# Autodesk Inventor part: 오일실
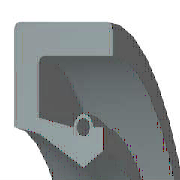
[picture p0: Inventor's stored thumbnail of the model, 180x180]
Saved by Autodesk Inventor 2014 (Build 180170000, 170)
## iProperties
IsCustomPart: 1
Created: 2015-12
Part Number: 오일실
Material: 고무
Description: 오일-실
Document SubType Name: Modeling
Standard: KS B 2804
Designer: mdu
Standards Organization: KS
Language: ko-KR
Size Designation: S - 15 30 7
Categories: <MemberInstance><Categories><Category DisplayName="샤프트 부품" InternalName="7f7aeb1f-a693-4053-b835-cee3144e0d98" Mnemonic="SHFT"><Category DisplayName="실링" Intern
Density: 1 g/cm^3
Appearance: 고무 - 검은색 - 버전 1.1
Mass: 1.76736 g
Surface Area: 26.6454 cm^2
Volume: 1.76736 cm^3
Author: mdu
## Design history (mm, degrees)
revolve "본체" stored, may be unused: angle "d17" = 90 deg
revolve "스프링1" stored, may be unused: angle "d18" = 90 deg
body "Solid1"
sketch "스케치1"
  geometry: L1 (0, 15)-(7, 15); L2 (7, 15)-(7, 13.75); L3 (7, 13.75)-(1.75, 13.75); L4 (0, 15)-(0, 9.6); L5 (0, 9.6)-(1.75, 9.25); L6 (1.75, 9.25)-(4.9, 7.5); L7 (4.9, 7.5)-(0, 7.5); L8 (6.3, 8.375)-(6.3, 9.6); L9 (0, 0)-(9.586, 0) reference; L10 (4.9, 7.5)-(6.3, 8.375); L11 (0, 18)-(0, -3) reference; L12 (-1.917, 0)-(11.503, 0) reference; L13 (4.2, 9.6)-(1.75, 10.09); L14 (1.75, 10.09)-(1.75, 13.75); L15 (6.3, 9.6)-(5.6, 9.6); C1 r 0.455 at (4.9, 9.6); A1 r 0.7 centre (4.9, 9.6) between (5.6, 9.6) and (4.2, 9.6)
  constraints: 26 end point, 5 horizontal alignment, 4 perpendicular, 2 centre point, 2 collinear, 2 horizontal, 2 parallel, 2 point on circle, 2 point on line, 2 vertical alignment, 1 coincident
  dimensions: "d0" = 30 diameter of L1 L9 (= SD2); "d1" = 16.75 diameter of L8.start L9 (= ABDM); "d2" = 1.25 distance of L1.end L2.end (computed from SD); "d3" = 0.91 diameter of C1 (= SPDI); "d4" = 1.4 diameter of A1 (= SPDA); "d5" = 15 diameter of L6.end L9 (= NND); "d6" = 18.5 diameter of L5.end L9 (= TKDM); "d7" = 19.2 diameter of L4.end L9 (= HLDM); "d8" = 4.9 distance from line of C1.centre L4 (= SPDST); "d9" = 6.3 distance between parallel lines of L8 L4 (= SDI); "d10" = 7 distance between parallel lines of L2 L4 (= SWDT); "d12" = 1.75 distance between parallel lines of L14 L4 (= SD)
fillet "모깎기1" dims "d11" = 0.3 (= RR)
other parameters: "SD2" = 30 [user parameter; used in 1 equation term], "SWDT" = 7 [user parameter; used in 1 equation term], "RR" = 0.3 [user parameter; used in 1 equation term], "SD" = 1.75 [user parameter; used in 2 equation terms], "NND" = 15 [user parameter; used in 1 equation term], "SPDA" = 1.4 [user parameter; used in 1 equation term], "SPDI" = 0.91 [user parameter; used in 1 equation term], "TKDM" = 18.5 [user parameter; used in 1 equation term], "HLDM" = 19.2 [user parameter; used in 1 equation term], "ABDM" = 16.75 [user parameter; used in 1 equation term], "SDI" = 6.3 [user parameter; used in 1 equation term], "SPDST" = 4.9 [user parameter; used in 1 equation term], "d13" = 0, "d14" = 0, "d15" = 0, "LAB" = 0.35 [user parameter]
